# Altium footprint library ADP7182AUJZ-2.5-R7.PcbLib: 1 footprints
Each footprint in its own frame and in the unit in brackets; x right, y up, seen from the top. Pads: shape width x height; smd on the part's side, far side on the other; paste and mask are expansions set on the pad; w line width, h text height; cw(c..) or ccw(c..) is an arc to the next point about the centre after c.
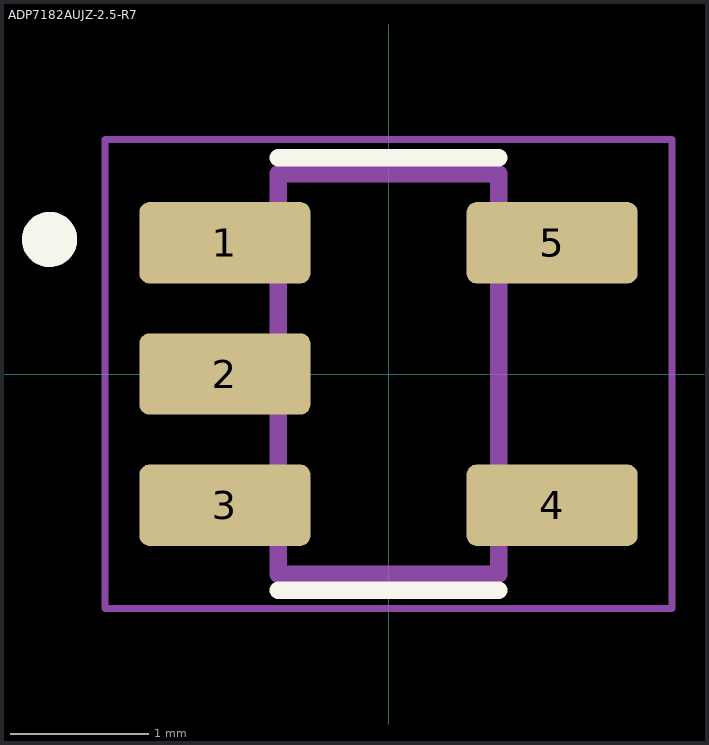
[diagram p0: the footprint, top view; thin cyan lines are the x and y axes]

## ADP7182AUJZ-2.5-R7 [mm]
pads (5):
  rrect25% 1.24x0.59 smd: 1(-1.185,0.95) 2(-1.185,0) 3(-1.185,-0.95) 4(1.185,-0.95) 5(1.185,0.95)
Top Overlay:
  circle w0.2: c-2.455,0.975 r0.1
  lines w0.127: -0.8,-1.565 0.8,-1.565 ; -0.8,1.565 0.8,1.565
Mechanical 13:
  circle w0.2: c-2.455,0.975 r0.1
  lines w0.127: -0.8,-1.45 -0.8,1.45 0.8,1.45 0.8,-1.45 -0.8,-1.45
Mechanical 15:
  lines w0.05: -2.055,-1.7 -2.055,1.7 2.055,1.7 2.055,-1.7 -2.055,-1.7
3D body "step_temp.STEP": height 1, standoff 0, extent -1.412,-1.429 1.388,1.471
